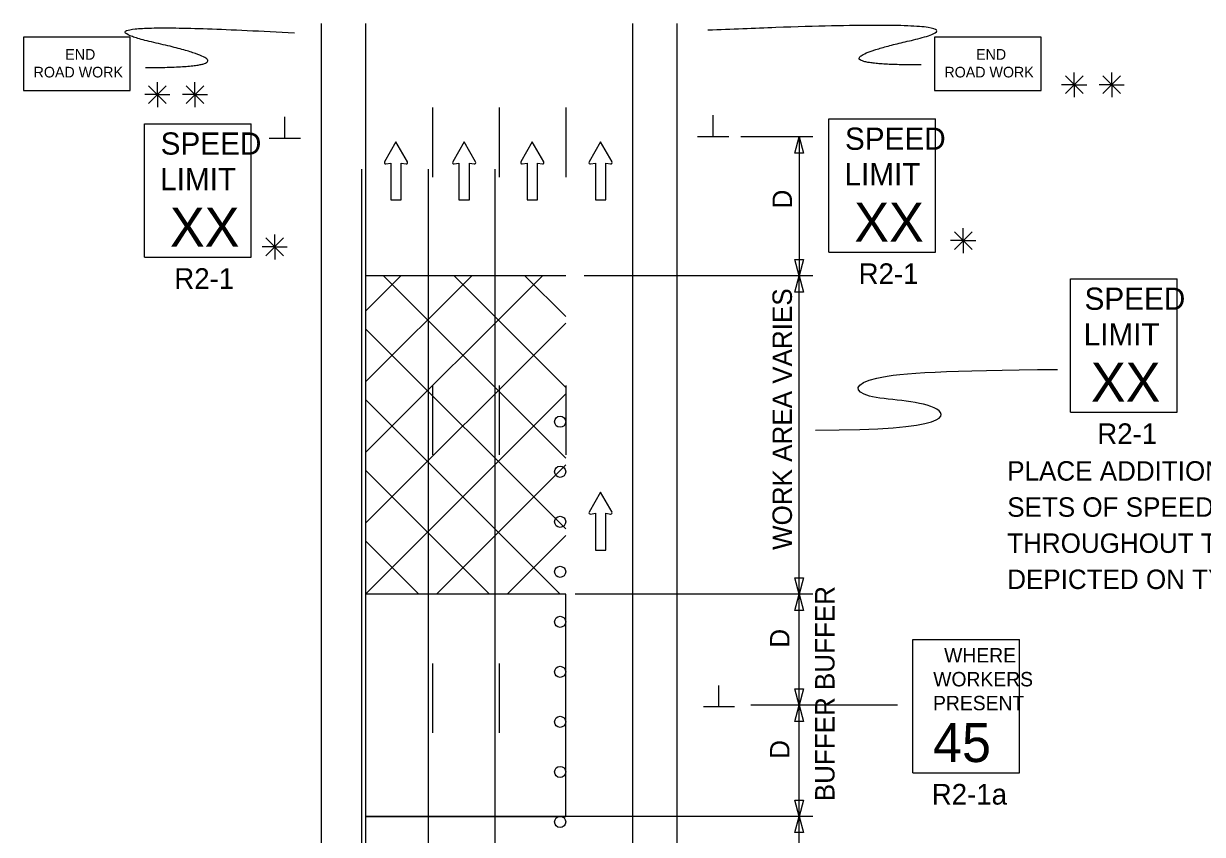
# Model space of a CAD drawing. Extents: x 16726 to 18475, y 5752 to 6929.
# Drawn here: x 16760.3 to 17184.6, y 6637.1 to 6928.9 of the extents above; entities that cross this region are included whole.
import ezdxf

# ---------------------------------------------------------------- set-up
doc = ezdxf.new("R2010")
doc.units = 0
for name, color, linetype in [('ALI_LEGAL_EX', 7, 'Continuous'), ('MT_SCRATCH_LEVEL_A', 7, 'Continuous'), ('MT_SCRATCH_LEVEL_E', 7, 'Continuous'), ('PAVT_EDGE_EX', 7, 'Continuous'), ('TRAFFIC_SIGNS_PR', 7, 'Continuous'), ('TYPICAL_TEXT_DIMEN_PR', 7, 'Continuous')]:
    doc.layers.add(name, color=color, linetype=linetype)

msp = doc.modelspace()

# ---------------------------------------------------------------- linework, layer by layer
at = {"layer": 'ALI_LEGAL_EX'}
for p, q in [((16881.97, 6876.43), (16881.97, 5996.39)), ((16905.97, 6876.43), (16905.97, 5996.39)), ((16929.97, 6876.43), (16929.97, 5996.39))]:
    msp.add_line(p, q, dxfattribs=at)
for points in [[(16907.45, 6898.64), (16907.45, 6873.64)], [(16931.45, 6898.64), (16931.45, 6873.64)], [(16955.45, 6898.64), (16955.45, 6873.64)], [(16907.45, 6798.64), (16907.45, 6773.64)], [(16931.45, 6798.64), (16931.45, 6773.64)], [(16955.45, 6798.64), (16955.45, 6773.64)], [(16907.45, 6698.64), (16907.45, 6673.64)], [(16931.45, 6698.64), (16931.45, 6673.64)]]:
    msp.add_lwpolyline(points, dxfattribs=at)
at = {"layer": 'MT_SCRATCH_LEVEL_A'}
for p, q in [((16955.45, 6838.13), (16883.45, 6838.13)), ((16883.45, 6838.13), (16883.45, 6694.17)), ((16955.45, 6838.13), (16883.45, 6838.13)), ((16883.45, 6838.13), (16883.45, 6723.59)), ((16883.45, 6825.42), (16896.16, 6838.13)), ((16883.45, 6799.96), (16921.61, 6838.13)), ((16883.45, 6774.51), (16947.07, 6838.13)), ((16955.45, 6772.51), (16889.83, 6838.13)), ((16955.45, 6797.97), (16915.28, 6838.13)), ((16955.45, 6823.42), (16940.74, 6838.13)), ((16883.45, 6749.05), (16955.45, 6821.05)), ((16955.45, 6747.05), (16883.45, 6819.05)), ((16883.45, 6723.59), (16955.45, 6795.59)), ((16953.45, 6723.59), (16883.45, 6793.6)), ((16927.99, 6723.59), (16883.45, 6768.14)), ((16908.9, 6723.59), (16955.45, 6770.14)), ((16902.54, 6723.59), (16883.45, 6742.69)), ((16934.36, 6723.59), (16955.45, 6744.68)), ((16955.45, 6723.59), (16883.45, 6723.59)), ((16883.45, 6723.59), (16883.45, 6694.17))]:
    msp.add_line(p, q, dxfattribs=at)
at = {"layer": 'MT_SCRATCH_LEVEL_E'}
for p, q in [((16894.36, 6886.31), (16890.25, 6879.07)), ((16898.5, 6879.07), (16894.36, 6886.31)), ((16918.89, 6886.31), (16914.77, 6879.07)), ((16923.03, 6879.07), (16918.89, 6886.31)), ((16943.41, 6886.31), (16939.3, 6879.07)), ((16947.56, 6879.07), (16943.41, 6886.31)), ((16967.97, 6886.31), (16963.86, 6879.07)), ((16972.12, 6879.07), (16967.97, 6886.31)), ((16890.73, 6878.39), (16892.5, 6878.7)), ((16892.5, 6878.7), (16892.5, 6865.45)), ((16896.25, 6865.45), (16896.25, 6878.7)), ((16896.25, 6878.7), (16898.02, 6878.39)), ((16915.26, 6878.39), (16917.03, 6878.7)), ((16917.03, 6878.7), (16917.03, 6865.45)), ((16920.78, 6865.45), (16920.78, 6878.7)), ((16920.78, 6878.7), (16922.55, 6878.39)), ((16939.79, 6878.39), (16941.56, 6878.7)), ((16941.56, 6878.7), (16941.56, 6865.45)), ((16945.3, 6865.45), (16945.3, 6878.7)), ((16945.3, 6878.7), (16947.08, 6878.39)), ((16964.34, 6878.39), (16966.12, 6878.7)), ((16966.12, 6878.7), (16966.12, 6865.45)), ((16969.86, 6865.45), (16969.86, 6878.7)), ((16969.86, 6878.7), (16971.64, 6878.39)), ((16892.5, 6865.45), (16896.25, 6865.45)), ((16917.03, 6865.45), (16920.78, 6865.45)), ((16941.56, 6865.45), (16945.3, 6865.45)), ((16966.12, 6865.45), (16969.86, 6865.45)), ((16967.97, 6760.29), (16963.86, 6753.05)), ((16972.12, 6753.05), (16967.97, 6760.29)), ((16964.34, 6752.37), (16966.12, 6752.68)), ((16966.12, 6752.68), (16966.12, 6739.43)), ((16969.86, 6739.43), (16969.86, 6752.68)), ((16969.86, 6752.68), (16971.64, 6752.37)), ((16966.12, 6739.43), (16969.86, 6739.43))]:
    msp.add_line(p, q, dxfattribs=at)
for centre, start, end in [((16890.65, 6878.85), 150.4248, 279.9638), ((16898.09, 6878.85), 260.0362, 29.7731), ((16915.18, 6878.85), 150.4248, 279.9638), ((16922.62, 6878.85), 260.0362, 29.7731), ((16939.71, 6878.85), 150.4248, 279.9638), ((16947.15, 6878.85), 260.0362, 29.7731), ((16964.27, 6878.85), 150.4248, 279.9638), ((16971.71, 6878.85), 260.0362, 29.7731), ((16964.27, 6752.83), 150.4248, 279.9638), ((16971.71, 6752.83), 260.0362, 29.7731)]:
    msp.add_arc(centre, 0.463, start, end, dxfattribs=at)
at = {"layer": 'PAVT_EDGE_EX'}
for p, q in [((16867.45, 6928.88), (16867.45, 6018.6)), ((16883.45, 6928.88), (16883.45, 6018.6)), ((16979.45, 6928.88), (16979.45, 6018.6)), ((16995.45, 6928.88), (16995.45, 6018.6))]:
    msp.add_line(p, q, dxfattribs=at)
msp.add_lwpolyline([(16955.45, 6723.59), (16883.45, 6723.59), (16883.45, 6643.59), (16955.45, 6643.59)], close=True, dxfattribs=at)
at = {"layer": 'TRAFFIC_SIGNS_PR'}
for p, q in [((16803.88, 6892.85), (16842.28, 6892.85)), ((16803.88, 6844.85), (16803.88, 6892.85)), ((16842.28, 6844.85), (16842.28, 6892.85)), ((17050.2, 6894.59), (17088.6, 6894.59)), ((17050.2, 6846.59), (17050.2, 6894.59)), ((17088.6, 6846.59), (17088.6, 6894.59)), ((16803.88, 6844.85), (16842.28, 6844.85)), ((17050.2, 6846.59), (17088.6, 6846.59)), ((17137.18, 6837.01), (17175.58, 6837.01)), ((17137.18, 6789.01), (17137.18, 6837.01)), ((17175.58, 6789.01), (17175.58, 6837.01)), ((17137.18, 6789.01), (17175.58, 6789.01)), ((17080.36, 6707.27), (17118.76, 6707.27)), ((17080.36, 6659.27), (17080.36, 6707.27)), ((17118.76, 6659.27), (17118.76, 6707.27)), ((17080.36, 6659.27), (17118.76, 6659.27))]:
    msp.add_line(p, q, dxfattribs=at)
for points in [[(16760.32, 6904.75), (16798.72, 6904.75), (16798.72, 6923.95), (16760.32, 6923.95)], [(17088.17, 6904.75), (17126.57, 6904.75), (17126.57, 6923.95), (17088.17, 6923.95)]]:
    msp.add_lwpolyline(points, close=True, dxfattribs=at)
for centre in [(16953.45, 6785.59), (16953.45, 6767.59), (16953.45, 6749.59), (16953.45, 6731.59), (16953.45, 6713.59), (16953.45, 6695.59), (16953.45, 6677.59), (16953.45, 6659.59), (16953.45, 6641.59), (16953.45, 6641.59)]:
    msp.add_circle(centre, 2, dxfattribs=at)
for points in [[(16804.24, 6913.06), (16846.75, 6913.06), (16770.23, 6930.47), (16857.78, 6925.53)], [(17083.45, 6913.98), (17040.94, 6913.98), (17117.46, 6931.39), (17006.67, 6926.45)]]:
    msp.add_open_spline(points, degree=2, dxfattribs=at)
at = {"layer": 'TYPICAL_TEXT_DIMEN_PR'}
for p, q in [((17135.32, 6910.06), (17141.69, 6903.68)), ((17141.69, 6910.06), (17135.32, 6903.68)), ((17138.5, 6906.87), (17138.5, 6911.33)), ((17148.82, 6910.06), (17155.2, 6903.68)), ((17155.2, 6910.06), (17148.82, 6903.68)), ((17152.01, 6906.87), (17152.01, 6911.33)), ((16805.31, 6906.51), (16811.68, 6900.13)), ((16811.68, 6906.51), (16805.31, 6900.13)), ((16808.5, 6903.32), (16808.5, 6907.78)), ((16825.19, 6906.51), (16818.81, 6900.13)), ((16818.82, 6906.51), (16825.19, 6900.13)), ((16822, 6903.32), (16822, 6907.78)), ((17138.5, 6906.87), (17133.97, 6906.87)), ((17138.5, 6906.87), (17141.69, 6906.87)), ((17138.5, 6906.87), (17142.98, 6906.87)), ((17138.5, 6906.87), (17138.5, 6902.37)), ((17152.01, 6906.87), (17147.48, 6906.87)), ((17152.01, 6906.87), (17155.2, 6906.87)), ((17152.01, 6906.87), (17156.49, 6906.87)), ((17152.01, 6906.87), (17152.01, 6902.37)), ((16808.5, 6903.32), (16803.96, 6903.32)), ((16808.5, 6903.32), (16811.68, 6903.32)), ((16808.5, 6903.32), (16812.97, 6903.32)), ((16808.5, 6903.32), (16808.5, 6898.82)), ((16822, 6903.32), (16817.47, 6903.32)), ((16822, 6903.32), (16825.19, 6903.32)), ((16822, 6903.32), (16826.48, 6903.32)), ((16822, 6903.32), (16822, 6898.82)), ((16854.32, 6887.59), (16854.32, 6895.38)), ((17008.57, 6888.13), (17008.57, 6895.92)), ((16848.7, 6887.59), (16859.95, 6887.59)), ((17014.2, 6888.13), (17002.95, 6888.13)), ((17044.45, 6888.13), (17018.45, 6888.13)), ((17037.88, 6882.27), (17039.45, 6888.13)), ((17039.45, 6888.13), (17039.45, 6838.13)), ((17039.45, 6888.13), (17041.02, 6882.27)), ((17039.45, 6882.27), (17037.88, 6882.27)), ((17041.02, 6882.27), (17039.45, 6882.27)), ((16850.71, 6848.53), (16850.71, 6852.99)), ((17095.36, 6853.98), (17101.73, 6847.6)), ((17101.73, 6853.98), (17095.36, 6847.6)), ((17098.54, 6850.79), (17098.54, 6855.24)), ((16847.53, 6851.72), (16853.9, 6845.35)), ((16853.9, 6851.72), (16847.53, 6845.35)), ((17098.54, 6850.79), (17094.01, 6850.79)), ((17098.54, 6850.79), (17101.73, 6850.79)), ((17098.54, 6850.79), (17103.02, 6850.79)), ((17098.54, 6850.79), (17098.54, 6846.29)), ((16850.71, 6848.53), (16846.18, 6848.53)), ((16850.71, 6848.53), (16853.9, 6848.53)), ((16850.71, 6848.53), (16855.19, 6848.53)), ((16850.71, 6848.53), (16850.71, 6844.03)), ((17039.45, 6838.13), (17037.88, 6843.99)), ((17037.88, 6843.99), (17039.45, 6843.99)), ((17039.45, 6843.99), (17041.02, 6843.99)), ((17041.02, 6843.99), (17039.45, 6838.13)), ((17044.45, 6838.13), (16962.05, 6838.13)), ((17037.88, 6832.27), (17039.45, 6838.13)), ((17039.45, 6723.59), (17039.45, 6838.13)), ((17039.45, 6838.13), (17041.02, 6832.27)), ((17039.45, 6832.27), (17037.88, 6832.27)), ((17041.02, 6832.27), (17039.45, 6832.27)), ((17039.45, 6723.59), (17037.88, 6729.46)), ((17037.88, 6729.46), (17039.45, 6729.46)), ((17039.45, 6729.46), (17041.02, 6729.46)), ((17041.02, 6729.46), (17039.45, 6723.59)), ((17044.45, 6723.59), (16958.82, 6723.59)), ((17037.88, 6717.73), (17039.45, 6723.59)), ((17039.45, 6683.59), (17039.45, 6723.59)), ((17039.45, 6723.59), (17041.02, 6717.73)), ((17039.45, 6717.73), (17037.88, 6717.73)), ((17041.02, 6717.73), (17039.45, 6717.73)), ((17010.63, 6682.96), (17010.63, 6690.74)), ((17039.45, 6683.59), (17037.88, 6689.46)), ((17037.88, 6689.46), (17039.45, 6689.46)), ((17039.45, 6689.46), (17041.02, 6689.46)), ((17041.02, 6689.46), (17039.45, 6683.59)), ((17074.88, 6683.59), (17022.11, 6683.59)), ((17037.88, 6677.73), (17039.45, 6683.59)), ((17039.45, 6643.59), (17039.45, 6683.59)), ((17039.45, 6683.59), (17041.02, 6677.73)), ((17016.25, 6682.96), (17005, 6682.96)), ((17039.45, 6677.73), (17037.88, 6677.73)), ((17041.02, 6677.73), (17039.45, 6677.73)), ((17039.45, 6643.59), (17037.88, 6649.46)), ((17037.88, 6649.46), (17039.45, 6649.46)), ((17039.45, 6649.46), (17041.02, 6649.46)), ((17041.02, 6649.46), (17039.45, 6643.59)), ((17044.45, 6643.59), (16883.45, 6643.59)), ((17037.88, 6637.73), (17039.45, 6643.59)), ((17039.45, 6613.03), (17039.45, 6643.59)), ((17039.45, 6643.59), (17041.02, 6637.73)), ((17039.45, 6637.73), (17037.88, 6637.73)), ((17041.02, 6637.73), (17039.45, 6637.73))]:
    msp.add_line(p, q, dxfattribs=at)
msp.add_open_spline([(17045.39, 6782.57), (17093.86, 6782.57), (17093.86, 6793.33), (17058.94, 6793.33), (17058.94, 6802.38), (17093.15, 6804.14), (17132.44, 6804.43)], degree=3, dxfattribs=at)

# ---------------------------------------------------------------- texts
at = {"layer": 'TRAFFIC_SIGNS_PR'}
for s, height, p in [('END', 3.831, (16775.32, 6915.88)), ('END', 3.831, (17103.17, 6915.88)), ('ROAD WORK', 3.831, (16763.93, 6909.49)), ('ROAD WORK', 3.831, (17091.77, 6909.49)), ('SPEED', 8, (17055.97, 6883.45)), ('SPEED', 8, (16809.65, 6881.71)), ('LIMIT', 8, (17055.81, 6870.65)), ('LIMIT', 8, (16809.49, 6868.91)), ('XX', 14.031, (16812.99, 6848.61)), ('XX', 14.031, (17059.32, 6850.35)), ('R2-1', 7.44, (16814.56, 6833.41)), ('R2-1', 7.44, (17060.88, 6835.15)), ('SPEED', 8, (17142.21, 6825.87)), ('LIMIT', 8, (17141.88, 6813.07)), ('XX', 14.031, (17144.49, 6792.77)), ('R2-1', 7.44, (17146.79, 6777.57)), ('PLACE ADDITIONAL SUPPLEMENTAL', 7, (17114.38, 6764.4)), ('SETS OF SPEED LIMIT SIGNS', 7, (17114.38, 6751.4)), ('THROUGHOUT THE WORK AREA AS', 7, (17114.38, 6738.4)), ('DEPICTED ON TYPICAL M0100a.', 7, (17114.38, 6725.4)), ('WHERE', 5.2, (17091.67, 6698.96)), ('WORKERS', 5.2, (17087.74, 6690.36)), ('PRESENT', 5.2, (17087.67, 6681.76)), ('45', 14.031, (17087.66, 6663.13)), ('R2-1a', 7.44, (17087.21, 6647.83))]:
    msp.add_text(s, height=height, dxfattribs=at).set_placement(p)
at = {"layer": 'TYPICAL_TEXT_DIMEN_PR'}
for s, p in [('D', (17036.89, 6862.35)), ('WORK AREA VARIES', (17036.89, 6739.45)), ('BUFFER', (17052.22, 6689.04)), ('D', (17035.99, 6704.3)), ('BUFFER', (17052.22, 6649.04)), ('D', (17035.99, 6664.3))]:
    msp.add_text(s, height=7, rotation=90, dxfattribs=at).set_placement(p)

doc.saveas('drawing.dxf')
